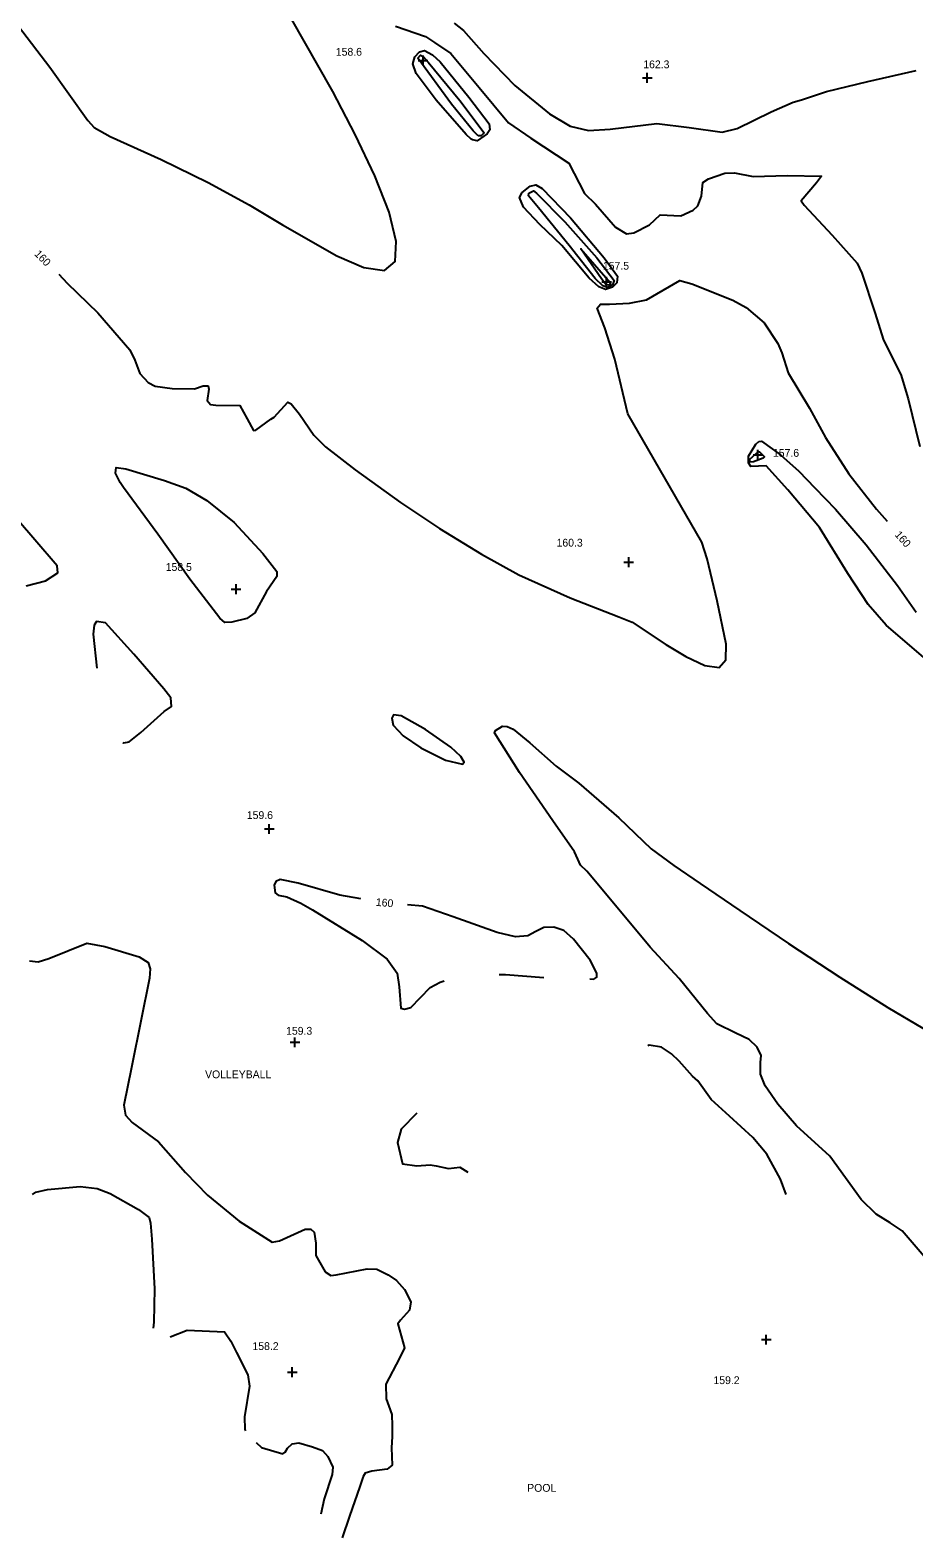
# Model space of a CAD drawing. Extents: x 1475150 to 2003689, y 770235 to 1112803.
# Drawn here: x 2000017.1 to 2000243.3, y 773826.4 to 774212.2 of the extents above; entities that cross this region are included whole.
import ezdxf

# ---------------------------------------------------------------- set-up
doc = ezdxf.new("R2010")
doc.units = 0
for name, color, linetype in [('RD_DTM_Major1', 7, 'Continuous'), ('RD_DTM_Major1_Lbl', 7, 'Continuous'), ('RD_DTM_Minor1', 7, 'Continuous'), ('RD_DTM_Spot_Elev', 7, 'Continuous'), ('RD_TX_Misc1', 7, 'Continuous')]:
    doc.layers.add(name, color=color, linetype=linetype)

msp = doc.modelspace()

# ---------------------------------------------------------------- linework, layer by layer
at = {"layer": 'RD_DTM_Major1'}
for points in [[(2000130, 774184.36), (2000128.74, 774185.57), (2000121.06, 774194.31), (2000115.87, 774201.19), (2000115.04, 774203.65), (2000115.55, 774205.42), (2000116.72, 774206.73), (2000118, 774207.05), (2000120.12, 774205.96), (2000122.04, 774204.1), (2000129.4, 774195.13), (2000134.57, 774188.24), (2000134.73, 774186.76), (2000134.04, 774185.74), (2000131.53, 774183.94), (2000130.32, 774184.16), (2000130, 774184.36)], [(2000143.03, 774170.69), (2000145.12, 774172.34), (2000146.57, 774172.64), (2000148.15, 774171.72), (2000155.45, 774164.19), (2000164.04, 774153.99), (2000167.47, 774149.24), (2000167.31, 774147.6), (2000166.19, 774146.49), (2000164.34, 774145.91), (2000162.65, 774146.52), (2000160.22, 774148.74), (2000153.2, 774157.11), (2000147.6, 774162.47), (2000143.38, 774166.98), (2000142.38, 774169.44), (2000143.03, 774170.69)], [(2000024.41, 774149.75), (2000026.61, 774147.52), (2000034.44, 774139.91), (2000042.58, 774130.4), (2000043.86, 774127.81), (2000045.19, 774124.37), (2000047.27, 774122.03), (2000049.11, 774121.15), (2000053.47, 774120.53), (2000059.13, 774120.41), (2000061.35, 774121.21), (2000062.64, 774121.21), (2000062.84, 774120.35), (2000062.4, 774117.5), (2000063.25, 774116.45), (2000064.62, 774116.28), (2000070.76, 774116.2), (2000072.63, 774112.77), (2000074.31, 774109.77), (2000074.85, 774109.9), (2000078.7, 774112.7), (2000079.54, 774113.21), (2000083.07, 774117.06), (2000083.93, 774116.62), (2000086.02, 774113.93), (2000089.67, 774108.57), (2000092.69, 774105.64), (2000100.33, 774099.74), (2000111.89, 774091.38), (2000121.84, 774084.72), (2000132.59, 774078.1), (2000142.16, 774072.85), (2000155.35, 774066.92), (2000167.81, 774062.06), (2000171.17, 774060.71), (2000179.8, 774055.01), (2000184.92, 774051.95), (2000189.81, 774049.66), (2000193.48, 774049.15), (2000195.18, 774051.12), (2000195.25, 774055.1), (2000192.93, 774066.17), (2000190.37, 774076.95), (2000188.99, 774081.17), (2000170.06, 774114.04), (2000166.73, 774128.06), (2000164.21, 774136.04), (2000162.22, 774141.06), (2000163.05, 774142.12), (2000165.41, 774142.11), (2000170.51, 774142.37), (2000174.89, 774143.2), (2000183.37, 774148.21), (2000186.47, 774147.32), (2000196.96, 774143.16), (2000200.41, 774141.28), (2000204.99, 774137.31), (2000208.47, 774132.09), (2000209.47, 774129.63), (2000211.16, 774124.52), (2000216.59, 774115.54), (2000220.66, 774107.99), (2000226.66, 774098.71), (2000233.76, 774089.64), (2000236.44, 774086.61)], [(2000016.08, 774069.99), (2000021.05, 774071.3), (2000024.18, 774073.33), (2000024.01, 774075.11), (2000018.33, 774081.77), (2000009.95, 774091.52), (2000007.61, 774094.24), (2000004.99, 774097.05), (2000004.26, 774097.34), (2000002.51, 774096.42), (1999995.61, 774090.57), (1999986.8, 774082.92), (1999974.75, 774071.88), (1999974.77, 774068.63), (1999975.4, 774067.24)], [(2000040.82, 774029.92), (2000041.04, 774029.82), (2000042.46, 774030.12), (2000045.47, 774032.47), (2000051.42, 774037.83), (2000053.25, 774039.13), (2000053.12, 774041.35), (2000051.31, 774043.64), (2000043.66, 774052.54), (2000036.36, 774060.54), (2000034.1, 774060.88), (2000033.47, 774059.92), (2000033.21, 774057.63), (2000034.18, 774048.97)], [(2000112.09, 774036.78), (2000110.14, 774036.99), (2000109.67, 774036.2), (2000110.03, 774034.36), (2000112.61, 774031.6), (2000117.13, 774028.54), (2000123.38, 774025.45), (2000127.75, 774024.36), (2000128.18, 774024.89), (2000127.33, 774026.37), (2000124.79, 774028.76), (2000118.27, 774033.29), (2000112.09, 774036.78)], [(2000101.76, 773989.96), (2000096.39, 773990.89), (2000085.68, 773993.97), (2000081.12, 773994.89), (2000080, 773994.4), (2000079.55, 773993.45), (2000079.79, 773991.46), (2000080.54, 773990.82), (2000082.83, 773990.47), (2000086.39, 773988.78), (2000089.37, 773987.12), (2000102.1, 773979.27), (2000108.46, 773974.47), (2000111.03, 773970.92), (2000111.59, 773967.36), (2000112.01, 773961.97), (2000112.96, 773961.71), (2000114.54, 773962.12), (2000119.53, 773967.2), (2000122.07, 773968.6), (2000123.05, 773968.91)], [(2000160.39, 773969.41), (2000161.37, 773969.39), (2000162.15, 773969.9), (2000162.17, 773970.88), (2000160.41, 773974.25), (2000156.19, 773979.64), (2000153.69, 773981.78), (2000151.15, 773982.7), (2000148.6, 773982.58), (2000146.51, 773981.59), (2000144.48, 773980.42), (2000141.31, 773980.21), (2000136.63, 773981.3), (2000125.39, 773985.28), (2000117.54, 773988.08), (2000113.67, 773988.42)], [(2000137.17, 773970.54), (2000138.77, 773970.54), (2000148.55, 773969.75)], [(2000210.6, 773914.22), (2000209.18, 773918.17), (2000205.7, 773924.58), (2000202.12, 773928.8), (2000196.1, 773934.28), (2000191.43, 773938.6), (2000188.03, 773943.37), (2000186.62, 773944.51), (2000183.22, 773948.36), (2000181.28, 773950.28), (2000178.7, 773951.96), (2000175.51, 773952.43), (2000175.22, 773952.3)], [(2000116.04, 773935.1), (2000112.07, 773930.97), (2000111.16, 773927.58), (2000112.43, 773922.08), (2000116.09, 773921.56), (2000119.53, 773921.84), (2000121.03, 773921.61), (2000124.18, 773920.94), (2000127.05, 773921.21), (2000129.17, 773919.95)], [(2000017.74, 773914.27), (2000018.52, 773914.89), (2000021.54, 773915.53), (2000029.92, 773916.31), (2000034.26, 773915.79), (2000037.56, 773914.54), (2000044.85, 773910.44), (2000047.57, 773908.36), (2000047.92, 773906.92), (2000048.23, 773902.84), (2000048.89, 773890.12), (2000048.79, 773881.54), (2000048.61, 773880.02)]]:
    msp.add_lwpolyline(points, dxfattribs=at)
at = {"layer": 'RD_DTM_Minor1'}
for points in [[(2000014.13, 774213.25), (2000022.16, 774202.75), (2000031.9, 774189.14), (2000033.52, 774187.33), (2000037.59, 774185.01), (2000050.63, 774179.11), (2000062.63, 774173.28), (2000073.16, 774167.5), (2000081.7, 774162.42), (2000095.6, 774154.46), (2000102.48, 774151.5), (2000107.76, 774150.74), (2000110.5, 774153.04), (2000110.79, 774158.18), (2000108.96, 774165.66), (2000105.33, 774174.98), (2000100.3, 774185.57), (2000094.54, 774196.53), (2000083.77, 774215.55)], [(2000110.64, 774213.26), (2000118.33, 774210.62), (2000120.61, 774209.09), (2000124.81, 774206.23), (2000132.02, 774197.58), (2000139.53, 774188.51), (2000145.26, 774184.59), (2000154.95, 774178.17), (2000159.01, 774170.46), (2000161.84, 774167.71), (2000166.97, 774161.8), (2000169.73, 774160.12), (2000171.66, 774160.34), (2000175.59, 774162.42), (2000178.34, 774164.94), (2000183.66, 774164.71), (2000186.85, 774166.2), (2000188.04, 774167.27), (2000188.93, 774169.73), (2000189.26, 774173.28), (2000190.7, 774174.23), (2000194.92, 774175.65), (2000197.43, 774175.76), (2000202.14, 774174.8), (2000210.85, 774175.06), (2000219.62, 774174.91), (2000218.41, 774173.17), (2000214.47, 774168.54), (2000215.19, 774167.44), (2000222.38, 774159.79), (2000228.8, 774152.62), (2000229.96, 774150.06), (2000233.32, 774139.98), (2000235.49, 774132.9), (2000239.93, 774124.14), (2000241.82, 774117.91), (2000244.87, 774105.66)], [(2000125.66, 774214.02), (2000128.06, 774212.16), (2000133.25, 774206.28), (2000141.13, 774198.1), (2000150.02, 774190.79), (2000155.34, 774187.63), (2000160.05, 774186.59), (2000165.53, 774186.9), (2000177.54, 774188.34), (2000185.79, 774187.35), (2000194.21, 774186.17), (2000198.03, 774187.07), (2000206.74, 774191.37), (2000212.4, 774193.83), (2000214.58, 774194.4), (2000220.91, 774196.58), (2000231.52, 774199.12), (2000243.87, 774201.94)], [(2000131.74, 774185.16), (2000130.49, 774186.49), (2000124.97, 774193.33), (2000116.37, 774205.06), (2000116.98, 774205.82), (2000117.7, 774205.54), (2000119, 774204.08), (2000127.06, 774194.21), (2000133.3, 774185.95), (2000132.56, 774185.18), (2000131.74, 774185.16)], [(2000144.77, 774170.49), (2000145.94, 774171.13), (2000146.71, 774170.51), (2000153.93, 774163.19), (2000162.12, 774153.94), (2000166.59, 774148.19), (2000166.15, 774147.02), (2000164.91, 774146.41), (2000163.66, 774146.77), (2000161.76, 774148.69), (2000155.08, 774157.14), (2000147.18, 774166.76), (2000144.69, 774169.85), (2000144.77, 774170.49)], [(2000165.25, 774146.94), (2000164.57, 774147.09), (2000163.31, 774148.64), (2000158.03, 774156.31), (2000165.66, 774147.58), (2000165.33, 774146.97), (2000165.25, 774146.94)], [(2000245.85, 774051.7), (2000236.18, 774059.99), (2000231.56, 774065.29), (2000226.43, 774073.22), (2000219.12, 774084.98), (2000211.06, 774094.63), (2000205.49, 774100.73), (2000201.57, 774100.59), (2000200.98, 774101.51), (2000201.01, 774103.24), (2000202.89, 774106.28), (2000203.63, 774106.98)], [(2000203.82, 774104.29), (2000205.1, 774103.06), (2000204.74, 774102.72), (2000202.25, 774101.77), (2000201.31, 774101.68), (2000201.32, 774102.41), (2000203.52, 774104.38), (2000203.82, 774104.29)], [(2000203.63, 774106.98), (2000204.27, 774107.01), (2000209.18, 774103.59), (2000213.86, 774099.35), (2000217.95, 774095.12), (2000223.24, 774089.63), (2000231.06, 774080.51), (2000239.14, 774070.14), (2000243.88, 774063.25)], [(2000040.13, 774096.44), (2000038.91, 774098.82), (2000039.14, 774100.28), (2000041.6, 774099.98), (2000051.52, 774096.95), (2000056.91, 774095.05), (2000062.35, 774091.9), (2000069.31, 774086.25), (2000076.63, 774078.31), (2000080.24, 774073.67), (2000080.25, 774072.45), (2000077.61, 774068.6), (2000074.58, 774063.1), (2000072.59, 774061.67), (2000068.72, 774060.69), (2000066.97, 774060.67), (2000065.62, 774061.79), (2000058.01, 774071.76), (2000049.77, 774083.28), (2000041, 774095.21), (2000040.13, 774096.44)], [(2000248.02, 773896), (2000240.29, 773904.92), (2000237.25, 773907.04), (2000233.69, 773909.21), (2000229.8, 773913.01), (2000221.78, 773924.02), (2000213.29, 773931.8), (2000208.44, 773937.33), (2000205.25, 773942.06), (2000204.07, 773945.05), (2000204.08, 773948.03), (2000204.19, 773949.85), (2000203.18, 773951.92), (2000201.1, 773953.9), (2000197.72, 773955.5), (2000192.85, 773957.92), (2000190.46, 773960.6), (2000183.26, 773969.55), (2000175.83, 773977.51), (2000169.03, 773985.66), (2000159.55, 773996.97), (2000158.01, 773998.53), (2000157.31, 774000.09), (2000156.44, 774001.95), (2000150.88, 774009.87), (2000142.37, 774022.22), (2000135.97, 774032.42), (2000136.24, 774033.02), (2000138.01, 774034.11), (2000139.16, 774034.05), (2000140.73, 774033.35), (2000145.01, 774029.87), (2000151.71, 774023.91), (2000157.53, 774019.55), (2000167.78, 774010.66), (2000176.1, 774002.72), (2000181.85, 773998.47), (2000188.57, 773993.82), (2000198.76, 773986.9), (2000211.23, 773978.53), (2000224.39, 773969.87), (2000236.64, 773962.07), (2000254.58, 773951.53)], [(2000016.94, 773974.07), (2000019.15, 773973.81), (2000021.9, 773974.67), (2000031.6, 773978.61), (2000036.25, 773977.7), (2000045, 773975.08), (2000047.33, 773973.65), (2000047.79, 773971.97), (2000047.62, 773969.58), (2000045.54, 773959.07), (2000043.06, 773946.76), (2000041.05, 773937.09), (2000041.53, 773934.56), (2000043.25, 773932.68), (2000049.96, 773927.76), (2000056.87, 773919.86), (2000062.48, 773914.07), (2000070.63, 773907.44), (2000079.06, 773902.01), (2000080.93, 773902.43), (2000087.49, 773905.35), (2000088.94, 773905.38), (2000089.8, 773904.62), (2000090.22, 773901.82), (2000090.21, 773898.61), (2000092.58, 773894.45), (2000094.03, 773893.51), (2000095.41, 773893.68), (2000103.36, 773895.26), (2000105.82, 773895.13), (2000108.77, 773893.66), (2000110.9, 773892.21), (2000112.92, 773889.96), (2000114.52, 773886.74), (2000114.17, 773884.68), (2000111.88, 773882.1), (2000111.21, 773881.16), (2000112.89, 773875.01), (2000111.68, 773872.35), (2000108.17, 773865.73), (2000108.19, 773861.97), (2000108.88, 773860.04), (2000109.64, 773857.97), (2000109.77, 773855.04), (2000109.74, 773852.34), (2000109.6, 773849.39), (2000109.76, 773844.99), (2000108.45, 773843.95), (2000104.53, 773843.48), (2000102.85, 773842.93), (2000102.37, 773842.08), (2000101.52, 773839.54), (2000098.86, 773831.93), (2000096.95, 773826.38)], [(2000052.93, 773877.79), (2000057.25, 773879.54), (2000066.83, 773879.11), (2000068.45, 773876.73), (2000069.95, 773873.8), (2000072.85, 773868.06), (2000073.26, 773865.18), (2000071.98, 773857.32), (2000072.04, 773854.15), (2000072.26, 773853.77)], [(2000074.96, 773850.78), (2000076.31, 773849.52), (2000081.79, 773847.88), (2000082.4, 773848.29), (2000083, 773849.34), (2000084.13, 773850.48), (2000085.9, 773850.66), (2000089.41, 773849.65), (2000091.89, 773848.75), (2000093.31, 773847.17), (2000094.59, 773844.46), (2000094.44, 773842.6), (2000092.35, 773836.4), (2000091.51, 773832.42)]]:
    msp.add_lwpolyline(points, dxfattribs=at)
at = {"layer": 'RD_DTM_Spot_Elev'}
for p, q in [((2000116.42, 774204.51), (2000118.92, 774204.51)), ((2000117.67, 774203.26), (2000117.67, 774205.76)), ((2000175.05, 774198.79), (2000175.05, 774201.29)), ((2000173.8, 774200.04), (2000176.3, 774200.04)), ((2000163.39, 774147.85), (2000165.89, 774147.85)), ((2000164.64, 774146.6), (2000164.64, 774149.1)), ((2000203.39, 774102.3), (2000203.39, 774104.8)), ((2000202.14, 774103.55), (2000204.64, 774103.55)), ((2000170.3, 774074.84), (2000170.3, 774077.34)), ((2000169.05, 774076.09), (2000171.55, 774076.09)), ((2000069.79, 774067.92), (2000069.79, 774070.42)), ((2000068.54, 774069.17), (2000071.04, 774069.17)), ((2000077.06, 774007.8), (2000079.56, 774007.8)), ((2000078.31, 774006.55), (2000078.31, 774009.05)), ((2000084.87, 773951.97), (2000084.87, 773954.47)), ((2000083.62, 773953.22), (2000086.12, 773953.22)), ((2000204.26, 773877.11), (2000206.76, 773877.11)), ((2000205.51, 773875.86), (2000205.51, 773878.36)), ((2000082.95, 773868.78), (2000085.45, 773868.78)), ((2000084.2, 773867.53), (2000084.2, 773870.03))]:
    msp.add_line(p, q, dxfattribs=at)

# ---------------------------------------------------------------- texts
at = {"layer": 'RD_DTM_Major1_Lbl'}
for rotation, p in [(314.5529, (2000018.02, 774154.82)), (311.4851, (2000238.27, 774083.02)), (354.9674, (2000105.52, 773988.14))]:
    msp.add_text('160', height=2, rotation=rotation, dxfattribs=at).set_placement(p)
at = {"layer": 'RD_DTM_Spot_Elev'}
for s, p in [('158.6', (2000095.34, 774205.7)), ('162.3', (2000174.04, 774202.49)), ('157.5', (2000163.7, 774150.94)), ('157.6', (2000207.23, 774103.05)), ('160.3', (2000151.84, 774080.07)), ('158.5', (2000051.8, 774073.85)), ('159.6', (2000072.56, 774010.35)), ('159.3', (2000082.61, 773955.14)), ('158.2', (2000074, 773874.45)), ('159.2', (2000192, 773865.73))]:
    msp.add_text(s, height=2, dxfattribs=at).set_placement(p)
at = {"layer": 'RD_TX_Misc1'}
for s, p in [('VOLLEYBALL', (2000061.87, 773944)), ('POOL', (2000144.33, 773838.17))]:
    msp.add_text(s, height=2, dxfattribs=at).set_placement(p)

doc.saveas('drawing.dxf')
